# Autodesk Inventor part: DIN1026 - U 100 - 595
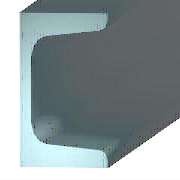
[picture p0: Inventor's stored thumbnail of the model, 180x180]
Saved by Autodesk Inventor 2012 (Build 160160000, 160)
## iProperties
Created: 2004-09
Part Number: DIN1026 - U 100 - 595
Material: Stahl (schweißbar)
Description: U-Profil
Vendor: Autodesk Inc.
Document SubType Name: Modeling
Standard: DIN1026
Designer: Greiling
Size Designation: U 100 - 595
Density: 1 g/cm^3
Checked By: Jürgen Kronas
Stock Number: 10-10005
Company: CAD-Verlag
Author: Juergen Kronas
Revision Number: 8
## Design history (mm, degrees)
sketch "Skizze"
  geometry: L1 (50, 0)-(0, 0); L2 (0, 0)-(0, 50); L3 (0, 50)-(6.5, 50); L4 (6.5, 50)-(10.02, 6); L5 (10.02, 6)-(50, 6); L6 (50, 6)-(50, 0); L7 (0, 25)-(8.5, 25); L8 (6.5, 50)-(8.5, 50); L9 (8.5, 50)-(8.5, 25); L10 (-20, 0)-(120, 0) reference; L11 (0, -10)-(0, 60) reference; L12 (50, 0)-(100, 0); L13 (100, 0)-(100, 50); L14 (100, 50)-(93.5, 50); L15 (93.5, 50)-(89.98, 6); L16 (89.98, 6)-(50, 6); 2 further points
  constraints: 28 end point, 6 symmetric about line, 4 parallel, 3 perpendicular, 2 collinear, 2 midpoint, 2 point on line, 1 horizontal, 5 other
  dimensions: "d0" = 6 distance between parallel lines of L1 L5 (= G_T); "d1" = 50 distance between parallel lines of L6 L2 (= 0.5 x G_H); "d2" = 50 distance between parallel lines of L3 L1 (= G_W); "d3" = 8.5 distance of L2.end L8.end (= G_T1); "d4" = 25 distance of L7.start L2.end (= G_C); "d5" = 2 distance of L3.end L8.end (computed from G_NG, G_T1)
extrude "Körper" new body sketch "Skizze" distance "d6" = 595 (= G_L); taper "d7" = 0 deg
workplane "Arbeitsebene1"
sketch "Skizze3"
  geometry: L1 (0, 64.266)-(595, 64.266) reference; L2 (0, 0)-(0, 64.266) reference; L3 (755.69, 32.133)-(-125.948, 32.133) reference; L4 (1.544, 32.133)-(629.742, 32.133); 4 further points
  constraints: 2 end point, 2 point on line, 1 horizontal, 1 vertical, 3 other
  dimensions: "d24" = 15 distance from line of L2 point (15, 52.633); "d25" = 20.5 distance from line of L3 point (15, 52.633); "d28" = 138 distance of point (15, 52.633) point (153, 52.633); "d31" = 41 distance of point (15, 52.633) point (15, 11.633)
hole "Bohrung1" sketch "Skizze3" at (15, 52.633), (153, 52.633), (15, 11.633), (153, 11.633) diameter "d34" = 12; stored, may be unused: countersink angle "d38" = 90 deg, drill point angle "d40" = 118 deg; dims "d35" = 6, "d36" = 4, "d37" = 2, "d39" = 8
node "Skizze4"
node "Volumenkörper1"
node "Volumenkörpern"
node "Oberflächenkörpern"
fillet "Rundung1" dims "d8" = 4.5 (= G_ER)
fillet "Rundung2" dims "d22" = 8.5 (= G_IR)
other parameters: "G_W" = 50 [user parameter; used in 1 equation term], "G_T" = 6 [user parameter; used in 1 equation term], "G_T1" = 8.5 [user parameter; used in 3 equation terms], "G_NG" = 2.35294 (computed from G_C, G_T1) [user parameter; used in 1 equation term], "G_ER" = 4.5 [user parameter; used in 1 equation term], "G_IR" = 8.5 [user parameter; used in 1 equation term], "G_C" = 25 [user parameter; used in 2 equation terms], "G_L" = 595 [user parameter; used in 1 equation term], "MAS" = 1.06 [user parameter], "G_IY" = 293 [user parameter], "G_WY" = 84.9 [user parameter], "G_RHO" = 0.0785 [user parameter]
